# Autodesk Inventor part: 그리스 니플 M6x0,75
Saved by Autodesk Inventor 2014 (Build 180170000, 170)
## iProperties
Created: 2026-04
Part Number: 그리스 니플 M6x0,75
Material: 일반
Document SubType Name: Modeling
Designer: dg
Density: 1 g/cm^3
Appearance: 기본값
Author: dg
Author: jhkim
Description: 윤활 니플, 원추 유형 A
Creation Date: 2026-03-26
Sending System: Autodesk Inventor 2026
Preprocessor: ST-DEVELOPER v20.1
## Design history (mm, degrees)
node "그리스 니플 M6x0,751"
body "Solid1"
node "기준1"
